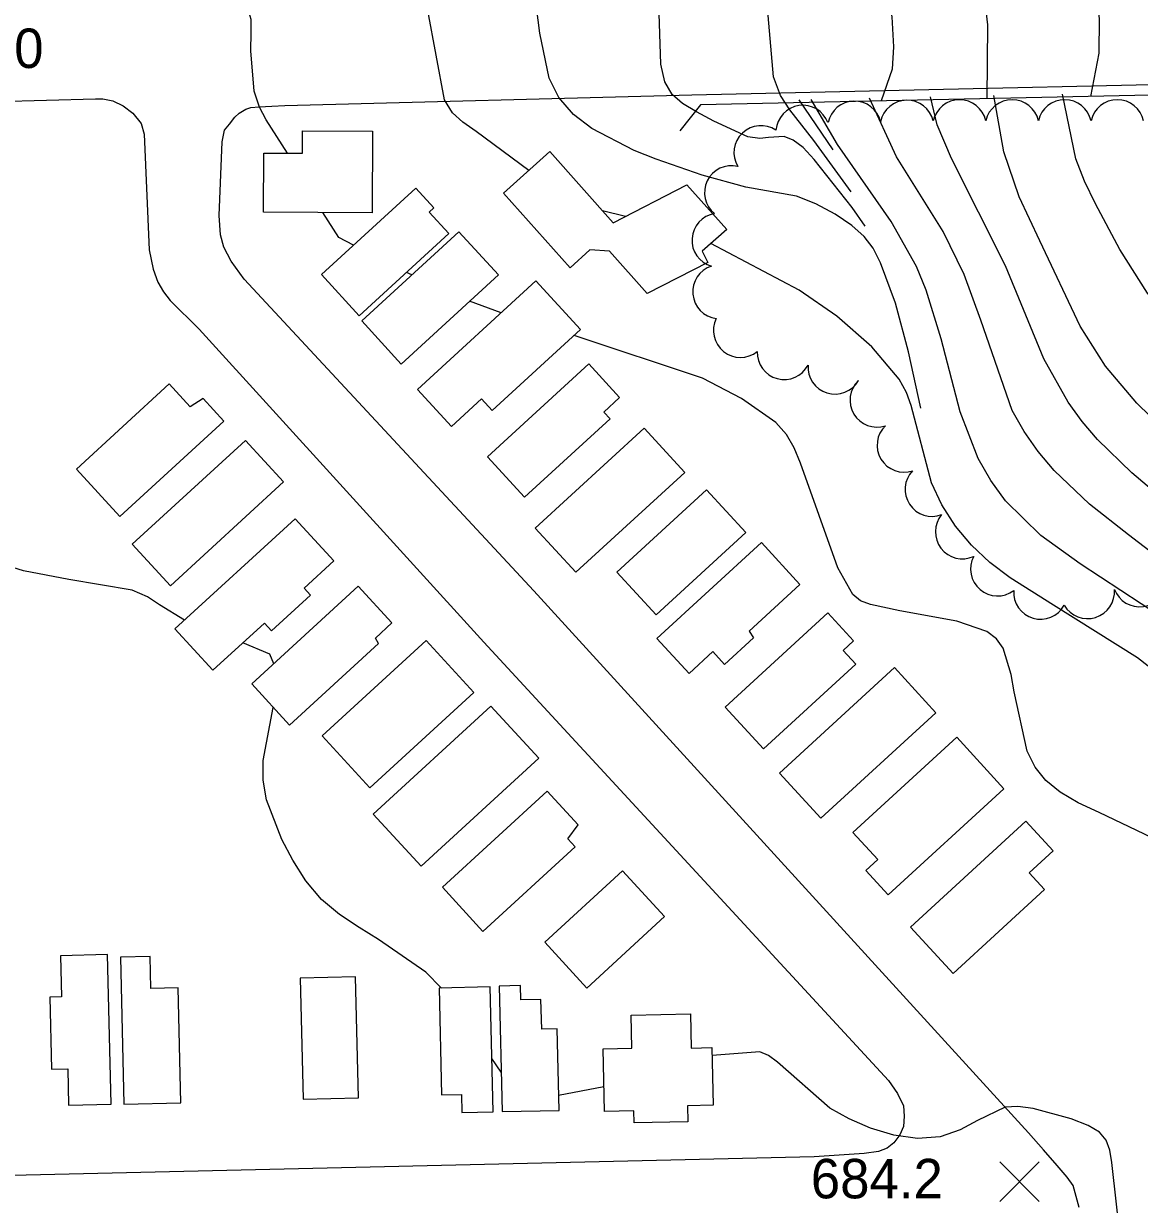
# Model space of a CAD drawing. Extents: x 79600 to 91800, y 75600 to 84400.
# Drawn here: x 87441.7 to 87865.8, y 78310.6 to 78759.5 of the extents above; entities that cross this region are included whole.
import ezdxf

# ---------------------------------------------------------------- set-up
doc = ezdxf.new("R2010")
doc.units = 0
for name, color, linetype in [('080-090$0$BLDG', 7, 'Continuous'), ('080-090$0$BRIDGE', 7, 'Continuous'), ('080-090$0$INDEX', 7, 'Continuous'), ('080-090$0$INTER', 7, 'Continuous'), ('080-090$0$ROAD', 7, 'Continuous'), ('080-090$0$SPOTMARK', 7, 'Continuous'), ('080-090$0$SPOTS', 7, 'Continuous'), ('080-090$0$TI_VER', 7, 'Continuous'), ('080-090$0$TREES', 7, 'Continuous')]:
    doc.layers.add(name, color=color, linetype=linetype)

# ---------------------------------------------------------------- blocks, each defined once
blk = doc.blocks.new('080-090$0$SPOTS')
at = {"layer": '080-090$0$SPOTMARK'}
for p, q in [((-0.5, -0.5), (0.5, 0.5)), ((-0.5, 0.5), (0.5, -0.5))]:
    blk.add_line(p, q, dxfattribs=at)

msp = doc.modelspace()

# ---------------------------------------------------------------- linework, layer by layer
at = {"layer": '080-090$0$BLDG'}
for points in [[(87533.02, 78710.31), (87547.65, 78710.23), (87547.69, 78718.82), (87574.3, 78718.68), (87574.13, 78687.6), (87532.9, 78687.82)], [(87641.7, 78710.84), (87665.83, 78683.75), (87693.83, 78698.28), (87708.97, 78681.28), (87699.62, 78672.95), (87701.8, 78668.64), (87678.7, 78656.94), (87664.41, 78672.98), (87656.97, 78673.46), (87649.37, 78666.69), (87624.05, 78695.12)], [(87603.27, 78679.71), (87595.78, 78687.87), (87597.58, 78689.52), (87590.73, 78696.97), (87554.92, 78664.09), (87569.25, 78648.48)], [(87622.16, 78664), (87585.23, 78630.11), (87570.2, 78646.49), (87607.12, 78680.38)], [(87653.39, 78643.24), (87619.84, 78612.44), (87615.76, 78616.88), (87604.29, 78606.35), (87591.4, 78620.39), (87636.43, 78661.72)], [(87668.2, 78617.39), (87662.17, 78611.86), (87664.58, 78609.24), (87632.11, 78579.43), (87618, 78594.8), (87656.5, 78630.14)], [(87509.87, 78616.97), (87504.96, 78613.85), (87496.99, 78622.53), (87461.74, 78590.17), (87478.28, 78572.15), (87517.75, 78608.38)], [(87692.98, 78588.92), (87651.61, 78550.95), (87636.17, 78567.76), (87677.54, 78605.74)], [(87540.46, 78585.3), (87497.44, 78545.81), (87482.95, 78561.59), (87525.97, 78601.08)], [(87716.19, 78566.01), (87682.15, 78534.76), (87667.21, 78551.03), (87701.25, 78582.28)], [(87559.6, 78555.24), (87548.34, 78544.9), (87550.77, 78542.26), (87535.93, 78528.64), (87533.18, 78531.63), (87513.61, 78513.67), (87499.18, 78529.39), (87544.84, 78571.31)], [(87736.78, 78546.29), (87717.46, 78528.55), (87719.11, 78525.97), (87708.16, 78515.92), (87703.68, 78520.8), (87694.62, 78512.49), (87682.43, 78525.77), (87722.15, 78562.23)], [(87528.39, 78508.49), (87542.75, 78492.85), (87576.52, 78523.85), (87575.37, 78525.91), (87581.63, 78531.66), (87568.83, 78545.61)], [(87757.12, 78524.85), (87753.22, 78521.26), (87758.02, 78516.03), (87722.96, 78483.85), (87708.4, 78499.71), (87747.37, 78535.47)], [(87555.15, 78488.73), (87573.29, 78468.97), (87612.77, 78505.21), (87594.63, 78524.97)], [(87788.51, 78497.54), (87744.78, 78457.4), (87728.97, 78474.62), (87772.7, 78514.77)], [(87592.73, 78439.17), (87637.46, 78480.23), (87619.33, 78499.98), (87574.6, 78458.92)], [(87814.35, 78468.67), (87770.38, 78428.31), (87761.83, 78437.62), (87766.37, 78441.79), (87756.94, 78452.06), (87796.37, 78488.26)], [(87616.28, 78414.41), (87651.37, 78446.62), (87648.59, 78449.65), (87652.52, 78454.87), (87640.7, 78467.75), (87600.87, 78431.2)], [(87833.03, 78445.01), (87823.9, 78436.62), (87829.71, 78430.29), (87795.01, 78398.43), (87778.86, 78416.02), (87822.7, 78456.26)], [(87655.77, 78392.89), (87685.33, 78420.02), (87669.35, 78437.42), (87639.8, 78410.29)], [(87455.63, 78405.18), (87455.99, 78389.51), (87451.68, 78389.41), (87452.31, 78362.05), (87458.44, 78362.19), (87458.76, 78348.3), (87474.91, 78348.67), (87473.6, 78405.59)], [(87490.05, 78392.74), (87489.77, 78404.87), (87478.54, 78404.61), (87479.81, 78348.74), (87501.37, 78349.24), (87500.37, 78392.98)], [(87546.83, 78396.69), (87547.88, 78350.61), (87568.93, 78351.09), (87567.88, 78397.17)], [(87599.61, 78392.83), (87600.54, 78352.28), (87608.12, 78352.45), (87608.27, 78345.6), (87620.1, 78345.87), (87619.01, 78393.28)], [(87638.6, 78377.29), (87638.34, 78388.54), (87630.68, 78388.37), (87630.55, 78393.82), (87622.5, 78393.63), (87623.59, 78345.89), (87645.19, 78346.38), (87644.48, 78377.42)], [(87672.92, 78370.07), (87672.64, 78382.58), (87695.19, 78383.09), (87695.49, 78370.08), (87703.34, 78370.26), (87703.85, 78348.36), (87694.03, 78348.14), (87694.17, 78342.04), (87673.81, 78341.57), (87673.7, 78346.18), (87662.47, 78345.92), (87661.92, 78369.82)]]:
    msp.add_lwpolyline(points, close=True, dxfattribs=at)
at = {"layer": '080-090$0$BRIDGE'}
for p, q in [((87934.81, 78733.66), (87698.99, 78728.68)), ((87698.99, 78728.68), (87691.09, 78718.8))]:
    msp.add_line(p, q, dxfattribs=at)
at = {"layer": '080-090$0$INDEX'}
msp.add_line((87670.44, 78686.14), (87661.69, 78688.4), dxfattribs=at)
for points in [[(87633.69, 78703.7), (87613.69, 78718.54), (87608.66, 78722.04), (87604.65, 78725.66), (87601.6, 78730.58), (87595.29, 78764.54), (87593.15, 78769.42), (87584.33, 78780.3), (87572.16, 78792.21), (87558.98, 78804.2), (87545.18, 78815.49), (87537.74, 78820.74), (87529.76, 78825.61), (87521.45, 78829.77), (87490.07, 78837.82), (87472.22, 78849.06)], [(87805.42, 78781.84), (87808.05, 78759), (87807.86, 78730.98)], [(88047.85, 78298.85), (88049.97, 78317.25), (88051.05, 78333.49), (88049.71, 78345.73), (88047.48, 78351.67), (88039.38, 78365.54), (88022.97, 78387.33), (88005.59, 78408.68), (87979.38, 78436.38), (87914.8, 78516.18), (87903.52, 78530.14), (87890.91, 78542.74), (87861.64, 78565.16), (87846.86, 78576.77), (87833.38, 78589.69), (87827.4, 78596.8), (87822.05, 78604.4), (87817.43, 78612.41), (87805.57, 78646.83), (87799.26, 78664.16), (87791.18, 78680.45), (87773.49, 78708.93), (87763.27, 78731.13)], [(88063.5, 78278.46), (88066.91, 78314.82), (88068.5, 78330.5), (88068.33, 78337.34), (88067.01, 78344.33), (88064.32, 78351.94), (88055.86, 78367.91), (88045.26, 78382.81), (87989.49, 78445.84), (87944.45, 78501.87), (87917.5, 78538.92), (87905.45, 78552.75), (87877.19, 78576.75), (87862.93, 78588.71), (87849.93, 78601.41), (87844.1, 78608.24), (87838.75, 78615.6), (87829.48, 78632.09), (87814.97, 78667.44), (87794.39, 78708.23), (87788.92, 78720.98), (87786.39, 78731.62)], [(88080.48, 78285.47), (88083.7, 78313.55), (88085.9, 78329.21), (88086.21, 78340.53), (88084.82, 78346.37), (88078.01, 78361.32), (88067.75, 78377.45), (88035.83, 78413.3), (87999.27, 78455.64), (87958.18, 78507.91), (87946.31, 78522.5), (87931.68, 78546.06), (87920.67, 78561.62), (87907.37, 78575.75), (87885.43, 78595.18), (87864.92, 78615.22), (87852.99, 78629.33), (87843.36, 78644.44), (87828.01, 78676.92), (87820.13, 78693.69), (87814.29, 78710.75), (87810.49, 78732.13)], [(88105.36, 78281.7), (88105.29, 78317.8), (88105.79, 78332.39), (88105.71, 78338.93), (88104.82, 78345.79), (88102.76, 78353.41), (88099.61, 78361.57), (88095.56, 78369.82), (88085.5, 78385.41), (88042.54, 78431.88), (88012.61, 78468.76), (87967.97, 78531.74), (87944.73, 78572.31), (87934.87, 78588.27), (87929.18, 78595.66), (87901.9, 78621.78), (87881.34, 78642.23), (87868.92, 78657.07), (87858.46, 78673.64), (87849.12, 78691.02), (87844.99, 78699.66), (87841.66, 78708.16), (87836.64, 78732.68)], [(87874.3, 78533.83), (87843.34, 78554.13), (87828.34, 78564.89), (87814.99, 78578.12), (87809.34, 78585.87), (87804.57, 78594.19), (87797.72, 78611.98), (87790.52, 78639.68), (87784.78, 78658.16), (87781.05, 78667.22), (87771.51, 78684.27), (87751.02, 78713.58), (87741.09, 78730.66)], [(87879.62, 78507.15), (87865.1, 78518.44), (87833.13, 78538.46), (87816.72, 78548.85), (87809.04, 78554.67), (87802.02, 78561.18), (87795.9, 78568.52), (87790.77, 78576.53), (87786.74, 78584.96), (87779.05, 78614.33), (87777.34, 78619.23), (87774.48, 78624.31), (87764.12, 78636.61), (87750.86, 78648.35), (87736.45, 78658.16), (87702.97, 78675.93)]]:
    msp.add_lwpolyline(points, dxfattribs=at)
at = {"layer": '080-090$0$INTER'}
for p, q in [((87749.4, 78711.59), (87736.47, 78730.56)), ((87589.23, 78663.96), (87587.17, 78664.94)), ((87623.21, 78649.59), (87611.2, 78653.94)), ((87623.25, 78360.86), (87619.64, 78366.03)), ((87662.25, 78355.34), (87645.06, 78352.01))]:
    msp.add_line(p, q, dxfattribs=at)
for points in [[(87782.78, 78613.32), (87778.08, 78634.8), (87773.06, 78653.18), (87767.43, 78668.59), (87764.62, 78674.13), (87761.25, 78678.63), (87756.57, 78682.77), (87750.18, 78687.03), (87742.82, 78690.97), (87735.54, 78693.92), (87716.2, 78697.38), (87699.67, 78701.92), (87682.09, 78707.97), (87673.71, 78711.29), (87657.7, 78719.62), (87650.67, 78725.01), (87645.12, 78731.39), (87641.49, 78738.81), (87637.84, 78755.95), (87629.63, 78820.45)], [(87541.96, 78710.26), (87533.91, 78722.89), (87531.27, 78727.75), (87529.24, 78733.9), (87528.06, 78749.21), (87528.19, 78756.09), (87528.1, 78761.12), (87526.96, 78764.85), (87523.81, 78768.19), (87510.21, 78775.28), (87501.26, 78778.1), (87476.21, 78781.82), (87467.41, 78784.53), (87462.49, 78789.3)], [(87765.14, 78780.63), (87769.3, 78772.44), (87771.75, 78762.09), (87772.35, 78750.7), (87771.88, 78742.16), (87767.63, 78730.13)], [(87847.87, 78783.12), (87850.49, 78761.32), (87850.46, 78748.23), (87847.2, 78731.81)], [(87761.52, 78682.54), (87756.61, 78689.6), (87742.24, 78707.92), (87738.04, 78712.4), (87734.26, 78715.25), (87730.85, 78716.63), (87724.86, 78716.26), (87721.5, 78715.81), (87716.98, 78716.45), (87704, 78722.37), (87697.44, 78726.03), (87692.12, 78729.2), (87688.15, 78732.61), (87685.45, 78737.34), (87683.89, 78744.08), (87683.17, 78767.13)], [(87756.26, 78695.6), (87742.1, 78715.08), (87733, 78726.71), (87729.38, 78732.21), (87726.79, 78739.31), (87724.19, 78768.37)], [(87567.11, 78675.29), (87561.51, 78678.18), (87555.35, 78687.7)], [(87882.13, 78444.56), (87850.56, 78459.56), (87842.61, 78463.3), (87835.67, 78467.34), (87830.24, 78471.76), (87826.18, 78476.84), (87823.21, 78482.94), (87818.25, 78505.53), (87817.15, 78512.1), (87814.09, 78522.12), (87811.49, 78525.66), (87807.8, 78528.42), (87796.37, 78532.34), (87774.77, 78536.29), (87763.66, 78538.7), (87759.86, 78540.14), (87756.85, 78542.47), (87751.14, 78552.63), (87736.98, 78592.42), (87734.62, 78598.28), (87731.73, 78603.28), (87727.58, 78607.91), (87714.56, 78617.02), (87699.68, 78624.67), (87650.91, 78640.96)], [(87502.76, 78532.68), (87493.35, 78538.54), (87488.76, 78541.54), (87482.86, 78544.17), (87458.84, 78548.15), (87441.66, 78551.5), (87423.99, 78556.89), (87397.14, 78567.76), (87372.99, 78579.22), (87321.39, 78608.67), (87291.83, 78622.86), (87279.97, 78630.4)], [(87536.77, 78516.18), (87535.2, 78519.83), (87525, 78524.12)], [(87600.56, 78392.85), (87594.52, 78398.94), (87576.63, 78411.29), (87569.17, 78415.83), (87561.77, 78420.77), (87554.92, 78426.59), (87548.98, 78433.63), (87543.97, 78441.43), (87539.8, 78449.39), (87534.01, 78464.42), (87532.77, 78471.84), (87532.78, 78479.35), (87536.58, 78499.56)], [(87864.22, 78260.36), (87862.21, 78265.47), (87855.39, 78326.49), (87854.54, 78331.3), (87853.15, 78335.06), (87850.64, 78338.05), (87846.35, 78340.68), (87839.95, 78343.19), (87825.41, 78347.07), (87819.66, 78347.87), (87814.78, 78347.53), (87804.24, 78342.51), (87797.65, 78338.91), (87790.06, 78336.29), (87781.53, 78335.72), (87772.52, 78336.98), (87763.65, 78339.59), (87755.44, 78343.09), (87748.09, 78347.22), (87728.28, 78364.65), (87724.89, 78367.17), (87721.51, 78368.6), (87703.41, 78367.21)]]:
    msp.add_lwpolyline(points, dxfattribs=at)
at = {"layer": '080-090$0$ROAD'}
for p, q in [((87695.72, 78732.38), (87988.1, 78739.04)), ((87236.26, 78724.79), (87469.04, 78730.96)), ((87469.04, 78730.96), (87471.83, 78730.9)), ((87471.83, 78730.9), (87475.59, 78730.12)), ((87541, 78728.39), (87695.72, 78732.38)), ((87475.59, 78730.12), (87479.45, 78728.22)), ((87479.45, 78728.22), (87483.16, 78725.48)), ((87523.63, 78725.43), (87526.18, 78727.05)), ((87526.18, 78727.05), (87528, 78727.57)), ((87528, 78727.57), (87531.22, 78727.91)), ((87531.22, 78727.91), (87535.97, 78728.09)), ((87535.97, 78728.09), (87541, 78728.39)), ((87483.16, 78725.48), (87486.28, 78721.51)), ((87519.91, 78721.32), (87521.92, 78723.93)), ((87521.92, 78723.93), (87523.63, 78725.43)), ((87486.28, 78721.51), (87487.45, 78717.44)), ((87487.45, 78717.44), (87489.41, 78673.57)), ((87517.11, 78714.55), (87518.04, 78718.99)), ((87518.04, 78718.99), (87519.91, 78721.32)), ((87515.93, 78686.52), (87517.11, 78714.55)), ((87516.47, 78679.25), (87515.93, 78686.52)), ((87517.76, 78674.48), (87516.47, 78679.25)), ((87489.41, 78673.57), (87490.92, 78666.14)), ((87520.58, 78669.25), (87517.76, 78674.48)), ((87525.45, 78662.31), (87520.58, 78669.25)), ((87490.92, 78666.14), (87492.62, 78661.22)), ((87492.62, 78661.22), (87494.78, 78657.54)), ((87635.6, 78543.9), (87525.45, 78662.31)), ((87494.78, 78657.54), (87497.36, 78654.28)), ((87497.36, 78654.28), (87508.42, 78643.42)), ((87508.42, 78643.42), (87616.6, 78524.37)), ((87823.64, 78337.81), (87635.6, 78543.9)), ((87616.6, 78524.37), (87770.49, 78357.69)), ((87770.49, 78357.69), (87773.87, 78352.73)), ((87773.87, 78352.73), (87776.14, 78348.07)), ((87776.14, 78348.07), (87776.47, 78344.16)), ((87776.1, 78340.26), (87774.78, 78337.08)), ((87776.47, 78344.16), (87776.1, 78340.26)), ((87774.78, 78337.08), (87772.48, 78334.06)), ((87829.36, 78331.41), (87823.64, 78337.81)), ((87769.92, 78332.02), (87766.68, 78330.7)), ((87772.48, 78334.06), (87769.92, 78332.02)), ((87834.53, 78325.43), (87829.36, 78331.41)), ((87742.22, 78328.73), (87234.66, 78316.9)), ((87761.22, 78329.98), (87742.22, 78328.73)), ((87766.68, 78330.7), (87761.22, 78329.98)), ((87838.34, 78321.02), (87834.53, 78325.43)), ((87840.64, 78317.76), (87838.34, 78321.02)), ((87842.97, 78309.48), (87840.64, 78317.76))]:
    msp.add_line(p, q, dxfattribs=at)
at = {"layer": '080-090$0$TREES'}
for centre, start, end in [((87737.89, 78718.22), 21.0967, 175.7359), ((87757.49, 78719.82), 13.6143, 168.2535), ((87777.49, 78720.15), 13.6143, 168.2535), ((87797.45, 78720.33), 12.7953, 167.4345), ((87817.45, 78720.34), 12.6454, 167.2846), ((87837.45, 78720.33), 12.6454, 167.2846), ((87857.45, 78720.32), 12.6454, 167.2846), ((87721.95, 78710.48), 56.0703, 210.7096), ((87710.77, 78695.27), 76.6861, 231.3253), ((87705.98, 78677.14), 99.0537, 253.6929), ((87706.28, 78657.56), 108.0257, 262.6649), ((87714.17, 78642.88), 153.8594, 308.4987), ((87730.79, 78634.46), 177.7842, 332.4235), ((87750.1, 78628.9), 175.4561, 330.0953), ((87766.07, 78616.38), 133.7261, 288.3653), ((87776.38, 78599.25), 133.7261, 288.3653), ((87787.01, 78582.43), 136.215, 290.8542), ((87798.53, 78566.28), 140.1708, 294.81), ((87811.9, 78552.2), 152.2006, 306.8398), ((87865.89, 78548.08), 200.9989, 355.6381), ((87828.27, 78543.36), 176.424, 331.0633), ((87846.11, 78543.55), 210.1681, 4.8074)]:
    msp.add_arc(centre, 10.25, start, end, dxfattribs=at)

# ---------------------------------------------------------------- block references
at = {"layer": '080-090$0$SPOTMARK', "xscale": 15, "yscale": 15}
msp.add_blockref('080-090$0$SPOTS', (87820.26, 78319.28), dxfattribs=at)

# ---------------------------------------------------------------- texts
at = {"layer": '080-090$0$SPOTS'}
msp.add_text('684.2', height=15, dxfattribs=at).set_placement((87740.92, 78312.92))
at = {"layer": '080-090$0$TI_VER'}
msp.add_text('682.40', height=15, dxfattribs=at).set_placement((87387.88, 78742.65))

doc.saveas('drawing.dxf')
